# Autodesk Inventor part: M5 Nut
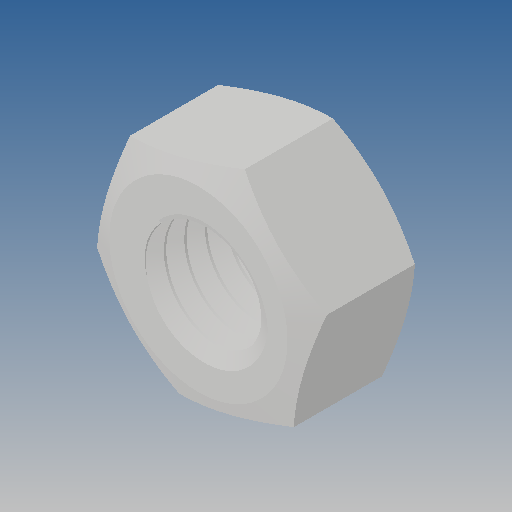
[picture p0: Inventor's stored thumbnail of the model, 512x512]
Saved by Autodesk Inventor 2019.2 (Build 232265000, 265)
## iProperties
Created: 2013-03
Part Number: M5 Nut
Material: Ogólny
Document SubType Name: Modeling
Designer: CADENGINEERING4
Density: 1 g/cm^3
Appearance: Domyślna
Author: CADENGINEERING4
Revision Number: ÈÎºÎ
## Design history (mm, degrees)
feature "ÇÐ³ý-É¨Ãè1"
node "Bryła1"
